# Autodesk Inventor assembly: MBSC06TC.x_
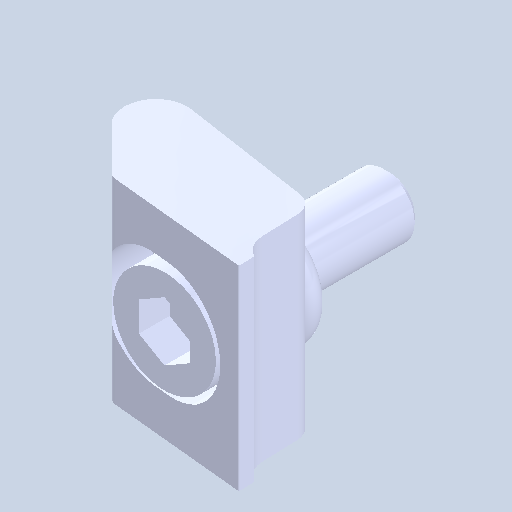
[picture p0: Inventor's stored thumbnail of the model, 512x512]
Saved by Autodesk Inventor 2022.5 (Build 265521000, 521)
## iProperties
Created: 2024-05
Part Number: MBSC06TC.x_
Document SubType Name: Assembly
Designer: ImaoCorp
Author: ImaoCorp
Sending System: SOLIDWORKS 2022-2022290
MC: AMD64
MC_MODEL: Intel64 Family 6 Model 60 Stepping 3, GenuineIntel
OS: Windows_NT
FRU: Parasolid Version 33.1, build 260,  4-25-2022
FORMAT: text
GUISE: transmit
KEY: FILEMBSC06TC.x_t
DATE: Mon May 20 16:28:02 2024
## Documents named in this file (4)
- X:\14_SW2022-Inv2022\保留中\mitee-bite\データ\mbsc06tc\MBSC06TC.x_.iam
- X:\14_SW2022-Inv2022\保留中\mitee-bite\データ\mbsc06tc\MBSC06TC_01.ipt
- X:\14_SW2022-Inv2022\保留中\mitee-bite\データ\mbsc06tc\MBSC06TC_02.ipt
- X:\14_SW2022-Inv2022\保留中\mitee-bite\データ\mbsc06tc\MBSC06TC_03.ipt
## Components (3 placed, 3 different names)
1. MBSC06TC_01
2. MBSC06TC_02
3. MBSC06TC_03
